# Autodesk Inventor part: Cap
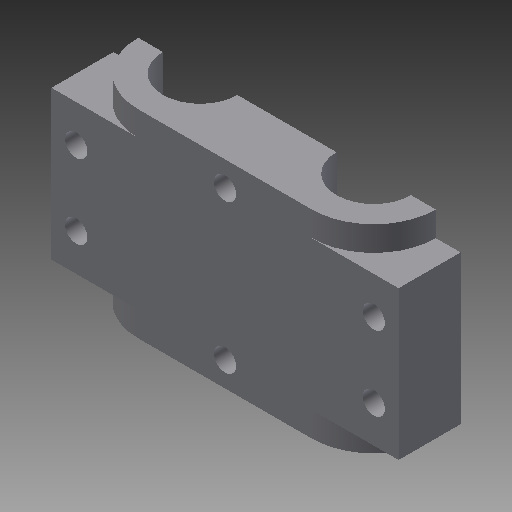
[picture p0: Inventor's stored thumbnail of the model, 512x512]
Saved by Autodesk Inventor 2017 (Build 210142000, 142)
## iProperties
Shininess: 77.0
Length Units: 11269
Angle Units: 11279
Time Units: 11290
Mass Units: 11283
Length Display Precision: 3
Angle Display Precision: 2
Created: 2002-02
Part Number: Cap
Document SubType Name: Modeling
Designer: ***
Density: 1 g/cm^3
Material: Generic
Appearance: Default
Density: 0.0
Volumn: 0.0
Area: 0.0
PropertySet Name: Model Information
Control State: 0
Master: False
Checked Out: False
Author: ***
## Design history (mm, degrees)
sketch "Sketch2"
  geometry: L1 (-17.5, 12.5)-(17.5, 12.5); L2 (30, 0)-(25, 0); L3 (10, 0)-(-10, 0); L4 (-25, 0)-(-30, 0); A1 r 12.5 centre (-17.5, 0) between (-17.5, 12.5) and (-30, 0); A2 r 12.5 centre (17.5, 0) between (30, 0) and (17.5, 12.5); A3 r 7.5 centre (17.5, 0) between (25, 0) and (10, 0); A4 r 7.5 centre (-17.5, 0) between (-10, 0) and (-25, 0)
  constraints: 8 end point, 8 point on circle, 4 centre point, 3 horizontal, 3 parallel, 2 coincident, 2 equal radius, 2 tangent
  dimensions: "d0" = 12.5 radius of A1; "d1" = 7.5 radius of A4; "d2" = 35 distance of A1.centre A2.centre; "d3" = 12.5 distance between parallel lines of L1 L3
extrude "Extrusion1" new body sketch "Sketch2" stored distance "d4" = 40; taper "d5" = 0 deg
workplane "Work Plane1"
sketch "Sketch3"
  geometry: L1 (-15, 12.5)-(15, 12.5); L2 (15, 12.5)-(15, 0); L3 (15, 0)-(-15, 0); L4 (-15, 0)-(-15, 12.5); L5 (-20, 0)-(20, 0) reference; L6 (-20, 12.5)-(20, 12.5) reference; L7 (20, 12.5)-(20, 0) reference
  constraints: 8 end point, 2 collinear, 2 parallel, 1 horizontal, 1 perpendicular
  dimensions: "d7" = 30 distance of L2.end L3.end; "d8" = 5 distance between parallel lines of L7 L2
extrude "Extrusion2" join sketch "Sketch3" stored distance "d9" = 40; taper "d10" = 0 deg
mirror "Mirror1"
sketch "Sketch4"
  geometry: L1 (-17.5, -35)-(0, -35) reference; L2 (-17.5, -35)-(-17.5, -5) reference; 1 further point
  dimensions: "d12" = 7.5 distance from line of L1 point (-12.5, -27.5); "d13" = 5 distance from line of L2 point (-12.5, -27.5)
hole "Hole1" sketch "Sketch4" at (-12.5, -27.5) diameter "d14" = 4.5; stored, may be unused: countersink angle "d18" = 82 deg, drill point angle "d20" = 118 deg; dims "d15" = 6, "d16" = 4, "d17" = 2, "d19" = 8
pattern_linear "Rectangular Pattern1" dims "d23" = 60, "d26" = 15
sketch "Sketch5"
  geometry: L1 (0, -40)-(35, -40) reference; L2 (-17.5, -35)-(-17.5, -5) reference; 1 further point
  dimensions: "d27" = 5 distance from line of L1 point (17.5, -35); "d28" = 35 distance from line of L2 point (17.5, -35)
hole "Hole2" sketch "Sketch5" at (17.5, -35) diameter "d29" = 4.5; stored, may be unused: countersink angle "d33" = 82 deg, drill point angle "d35" = 118 deg; dims "d30" = 6, "d31" = 4, "d32" = 2, "d34" = 8
pattern_linear "Rectangular Pattern2" dims "d38" = 30
body "Solid1"
other parameters: "d11" = 35
